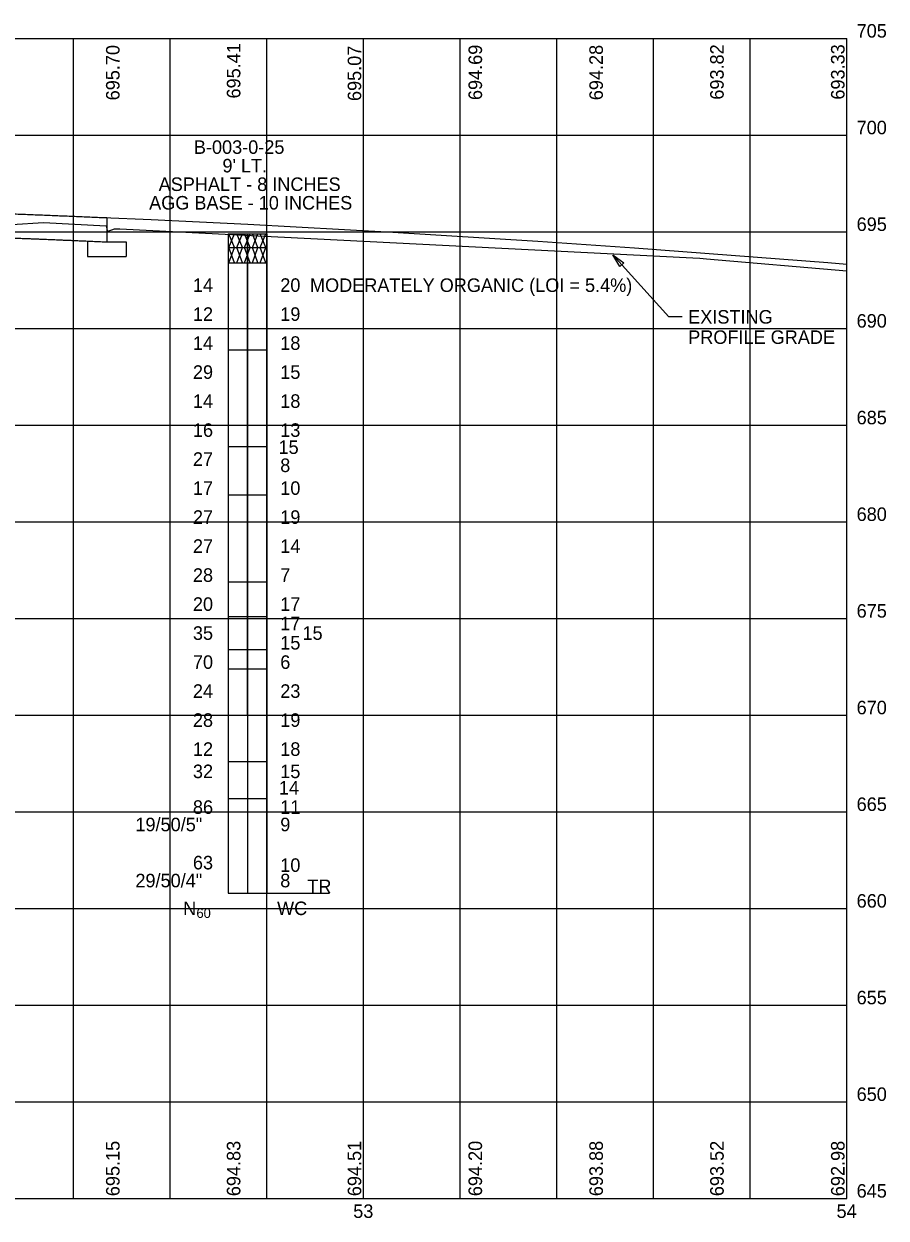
# Model space of a CAD drawing. Extents: x 991 to 1508, y 566 to 813.
# Drawn here: x 1329.7 to 1508.1, y 566 to 813 of the extents above; entities that cross this region are included whole.
import ezdxf

# ---------------------------------------------------------------- set-up
doc = ezdxf.new("R2010")
doc.units = 0
for name, color, linetype in [('BR_P_Gen_Approach_Slab', 7, 'Continuous'), ('Default', 7, 'Continuous'), ('GT_Project_Soil_Boring', 7, 'Continuous'), ('GT_Project_Soil_Layers', 7, 'Continuous'), ('GT_Project_Text', 7, 'Continuous'), ('GT_Project_Text_2', 7, 'Continuous'), ('PF_P_Grade_Line', 7, 'Continuous'), ('PF_P_Sta_Elev_Text', 7, 'Continuous'), ('PF_P_Text_Strip_Grades_20', 7, 'Continuous'), ('PF_X_Ground_Line', 7, 'Continuous'), ('PF_X_Text_Strip_Grade', 7, 'Continuous'), ('SC_Scratch1', 7, 'Continuous'), ('SH_Major_Grid_Line', 7, 'Continuous'), ('SH_Named_Boundary', 7, 'Continuous'), ('SH_Text', 7, 'Continuous')]:
    doc.layers.add(name, color=color, linetype=linetype)

msp = doc.modelspace()

# ---------------------------------------------------------------- linework, layer by layer
at = {"layer": 'BR_P_Gen_Approach_Slab'}
for p, q in [((1346.87, 772.95), (1346.87, 767.94)), ((1342.87, 768.11), (1342.87, 764.94)), ((1346.87, 767.94), (1350.87, 767.94)), ((1350.87, 767.94), (1350.87, 764.94)), ((1342.87, 764.94), (1350.87, 764.94))]:
    msp.add_line(p, q, dxfattribs=at)
for points in [[(1321.87, 773.95), (1334.37, 773.49), (1346.87, 772.95)], [(1323.63, 768.88), (1331.31, 768.6), (1338.98, 768.28), (1346.87, 767.94)]]:
    msp.add_open_spline(points, degree=2, dxfattribs=at)
at = {"layer": 'Default'}
msp.add_lwpolyline([(1326.04, 773.8), (1336.04, 773.4), (1346.04, 772.98), (1356.04, 772.54), (1366.04, 772.07), (1376.04, 771.57), (1386.04, 771.05), (1396.04, 770.5), (1406.04, 769.93), (1416.04, 769.34), (1426.04, 768.71), (1436.04, 768.07), (1446.04, 767.39), (1456.04, 766.69), (1466.04, 765.97), (1476.04, 765.22), (1486.04, 764.45), (1496.04, 763.64), (1500, 763.32)], dxfattribs=at)
at = {"layer": 'GT_Project_Soil_Boring'}
for p, q in [((1371.95, 769.6), (1379.95, 769.6)), ((1371.95, 769.6), (1371.95, 633.2)), ((1375.95, 769.6), (1375.95, 633.2)), ((1379.95, 769.6), (1379.95, 633.2)), ((1371.95, 766.8), (1379.95, 766.8)), ((1371.95, 763.6), (1379.95, 763.6)), ((1371.95, 745.6), (1379.95, 745.6)), ((1371.95, 725.6), (1379.95, 725.6)), ((1371.95, 715.6), (1379.95, 715.6)), ((1371.95, 697.6), (1379.95, 697.6)), ((1371.95, 690.4), (1379.95, 690.4)), ((1371.95, 683.6), (1379.95, 683.6)), ((1371.95, 679.6), (1379.95, 679.6)), ((1371.95, 660.4), (1379.95, 660.4)), ((1371.95, 652.8), (1379.95, 652.8)), ((1371.95, 633.2), (1379.95, 633.2))]:
    msp.add_line(p, q, dxfattribs=at)
at = {"layer": 'GT_Project_Soil_Layers'}
for p, q in [((1372.14, 766.8), (1373.29, 769.6)), ((1373.29, 766.8), (1372.14, 769.6)), ((1373.76, 766.8), (1374.91, 769.6)), ((1374.91, 766.8), (1373.76, 769.6)), ((1375.37, 766.8), (1376.53, 769.6)), ((1376.53, 766.8), (1375.37, 769.6)), ((1376.99, 766.8), (1378.14, 769.6)), ((1378.14, 766.8), (1376.99, 769.6)), ((1378.61, 766.8), (1379.76, 769.6)), ((1379.76, 766.8), (1378.61, 769.6)), ((1371.95, 766.8), (1371.95, 766.8)), ((1372.14, 763.6), (1373.29, 766.8)), ((1373.29, 763.6), (1372.14, 766.8)), ((1373.76, 763.6), (1374.91, 766.8)), ((1374.91, 763.6), (1373.76, 766.8)), ((1375.37, 763.6), (1376.53, 766.8)), ((1376.53, 763.6), (1375.37, 766.8)), ((1376.99, 763.6), (1378.14, 766.8)), ((1378.14, 763.6), (1376.99, 766.8)), ((1378.61, 763.6), (1379.76, 766.8)), ((1379.76, 763.6), (1378.61, 766.8)), ((1371.95, 763.6), (1371.95, 763.6))]:
    msp.add_line(p, q, dxfattribs=at)
at = {"layer": 'GT_Project_Text'}
for p, q in [((1379.95, 633.2), (1392.95, 633.2)), ((1365.41, 630.06), (1365.41, 630.06))]:
    msp.add_line(p, q, dxfattribs=at)
at = {"layer": 'PF_P_Grade_Line'}
msp.add_lwpolyline([(1326.04, 773.8), (1336.04, 773.4), (1346.04, 772.98), (1356.04, 772.54), (1366.04, 772.07), (1376.04, 771.57), (1386.04, 771.05), (1396.04, 770.5), (1406.04, 769.93), (1416.04, 769.34), (1426.04, 768.71), (1436.04, 768.07), (1446.04, 767.39), (1456.04, 766.69), (1466.04, 765.97), (1476.04, 765.22), (1486.04, 764.45), (1496.04, 763.64), (1500, 763.32)], dxfattribs=at)
at = {"layer": 'PF_X_Ground_Line'}
msp.add_lwpolyline([(1320.6, 771.15), (1333.77, 771.98), (1333.77, 771.98), (1346.7, 771.24), (1346.76, 771.23), (1346.95, 770.29), (1346.98, 770.31), (1347.13, 770.16), (1348.48, 770.67), (1349.58, 770.61), (1468.08, 764.61), (1469.54, 764.54), (1470.97, 764.42), (1500, 761.92)], dxfattribs=at)
at = {"layer": 'SC_Scratch1'}
msp.add_lwpolyline([(1300, 670), (1375.95, 670), (1375.95, 769.6)], dxfattribs=at)
at = {"layer": 'SH_Major_Grid_Line'}
for p, q in [((1000, 810), (1500, 810)), ((1000, 810), (1500, 810)), ((1000, 810), (1500, 810)), ((1340, 570), (1340, 810)), ((1340, 570), (1340, 810)), ((1360, 570), (1360, 810)), ((1360, 570), (1360, 810)), ((1380, 670), (1380, 810)), ((1380, 570), (1380, 810)), ((1400, 570), (1400, 810)), ((1400, 570), (1400, 810)), ((1420, 570), (1420, 810)), ((1420, 570), (1420, 810)), ((1440, 570), (1440, 810)), ((1440, 570), (1440, 810)), ((1460, 570), (1460, 810)), ((1460, 570), (1460, 810)), ((1480, 570), (1480, 810)), ((1480, 570), (1480, 810)), ((1500, 570), (1500, 810)), ((1500, 570), (1500, 810)), ((1000, 790), (1500, 790)), ((1000, 790), (1500, 790)), ((1000, 770), (1500, 770)), ((1000, 770), (1500, 770)), ((1000, 750), (1500, 750)), ((1000, 750), (1500, 750)), ((1000, 730), (1500, 730)), ((1000, 730), (1500, 730)), ((1000, 710), (1500, 710)), ((1000, 710), (1500, 710)), ((1000, 690), (1500, 690)), ((1000, 690), (1500, 690)), ((1000, 670), (1500, 670)), ((1000, 650), (1500, 650)), ((1000, 630), (1500, 630)), ((1000, 610), (1500, 610)), ((1000, 590), (1500, 590)), ((1000, 570), (1500, 570))]:
    msp.add_line(p, q, dxfattribs=at)
at = {"layer": 'SH_Named_Boundary'}
msp.add_line((1500, 570), (1500, 810), dxfattribs=at)
at = {"layer": 'SH_Text'}
for p in [(1451.54, 765.29), (1465.93, 752.43)]:
    msp.add_line(p, (1463.13, 752.43), dxfattribs=at)
msp.add_lwpolyline([(1453, 762.83), (1451.54, 765.29), (1453.83, 763.58)], close=True, dxfattribs=at)

# ---------------------------------------------------------------- texts
at = {"layer": 'GT_Project_Text'}
for s, height, p in [('B-003-0-25', 2.8, (1364.88, 786.15)), ('ASPHALT - 8 INCHES', 2.8, (1357.59, 778.47)), ('AGG BASE - 10 INCHES', 2.8, (1355.62, 774.63)), ('14', 2.8, (1364.68, 757.6)), ('20', 2.8, (1382.75, 757.6)), ('12', 2.8, (1364.68, 751.6)), ('19', 2.8, (1382.75, 751.6)), ('14', 2.8, (1364.68, 745.6)), ('18', 2.8, (1382.75, 745.6)), ('29', 2.8, (1364.68, 739.6)), ('15', 2.8, (1382.75, 739.6)), ('14', 2.8, (1364.68, 733.6)), ('18', 2.8, (1382.75, 733.6)), ('16', 2.8, (1364.68, 727.6)), ('13', 2.8, (1382.75, 727.6)), ('15', 2.8, (1382.39, 724.07)), ('27', 2.8, (1364.68, 721.6)), ('8', 2.8, (1382.75, 720.32)), ('17', 2.8, (1364.68, 715.6)), ('10', 2.8, (1382.75, 715.6)), ('27', 2.8, (1364.68, 709.6)), ('19', 2.8, (1382.75, 709.6)), ('27', 2.8, (1364.68, 703.6)), ('14', 2.8, (1382.75, 703.6)), ('28', 2.8, (1364.68, 697.6)), ('7', 2.8, (1382.75, 697.6)), ('20', 2.8, (1364.68, 691.6)), ('17', 2.8, (1382.75, 691.6)), ('17', 2.8, (1382.75, 687.6)), ('35', 2.8, (1364.68, 685.6)), ('15', 2.8, (1387.35, 685.6)), ('15', 2.8, (1382.75, 683.6)), ('70', 2.8, (1364.68, 679.6)), ('6', 2.8, (1382.75, 679.6)), ('24', 2.8, (1364.68, 673.6)), ('23', 2.8, (1382.75, 673.6)), ('28', 2.8, (1364.68, 667.6)), ('19', 2.8, (1382.75, 667.6)), ('12', 2.8, (1364.68, 661.6)), ('18', 2.8, (1382.75, 661.6)), ('32', 2.8, (1364.68, 656.99)), ('15', 2.8, (1382.75, 656.99)), ('14', 2.8, (1382.47, 653.6)), ('86', 2.8, (1364.68, 649.6)), ('11', 2.8, (1382.75, 649.6)), ('19/50/5"', 2.8, (1352.78, 646)), ('9', 2.8, (1382.75, 646)), ('63', 2.8, (1364.68, 638.11)), ('10', 2.8, (1382.75, 637.6)), ('29/50/4"', 2.8, (1352.78, 634.4)), ('8', 2.8, (1382.75, 634.4)), ('TR', 2.8, (1388.35, 633.2)), ('N', 2.8, (1362.65, 628.66)), ('60', 2, (1365.41, 628.06)), ('WC', 2.8, (1382.09, 628.66))]:
    msp.add_text(s, height=height, dxfattribs=at).set_placement(p)
at = {"layer": 'GT_Project_Text_2'}
msp.add_text("9' LT.", height=2.8, dxfattribs=at).set_placement((1370.79, 782.31))
at = {"layer": 'PF_P_Sta_Elev_Text'}
for s, p in [('705', (1502, 810.2)), ('705', (1502, 810.2)), ('700', (1502, 790.2)), ('700', (1502, 790.2)), ('695', (1502, 770.2)), ('695', (1502, 770.2)), ('690', (1502, 750.2)), ('690', (1502, 750.2)), ('685', (1502, 730.2)), ('685', (1502, 730.2)), ('680', (1502, 710.2)), ('680', (1502, 710.2)), ('675', (1502, 690.2)), ('675', (1502, 690.2)), ('670', (1502, 670.2)), ('670', (1502, 670.2)), ('665', (1502, 650.2)), ('660', (1502, 630.2)), ('655', (1502, 610.2)), ('650', (1502, 590.2)), ('645', (1502, 570.2)), ('53', (1397.85, 566)), ('54', (1497.85, 566))]:
    msp.add_text(s, height=2.8, dxfattribs=at).set_placement(p)
at = {"layer": 'PF_P_Text_Strip_Grades_20'}
for s, p in [('695.70', (1349.5, 797.22)), ('695.70', (1349.5, 797.22)), ('695.41', (1374.5, 797.61)), ('695.41', (1374.5, 797.61)), ('695.07', (1399.5, 797.08)), ('695.07', (1399.5, 797.08)), ('694.69', (1424.5, 797.28)), ('694.69', (1424.5, 797.28)), ('694.28', (1449.5, 797.25)), ('694.28', (1449.5, 797.25)), ('693.82', (1474.5, 797.36)), ('693.82', (1474.5, 797.36)), ('693.33', (1499.5, 797.37)), ('693.33', (1499.5, 797.37))]:
    msp.add_text(s, height=2.8, rotation=90, dxfattribs=at).set_placement(p)
at = {"layer": 'PF_X_Text_Strip_Grade'}
for s, p in [('695.15', (1349.5, 570.5)), ('695.15', (1349.5, 570.5)), ('694.83', (1374.5, 570.5)), ('694.51', (1399.5, 570.5)), ('694.20', (1424.5, 570.5)), ('694.20', (1424.5, 570.5)), ('693.88', (1449.5, 570.5)), ('693.52', (1474.5, 570.5)), ('692.98', (1499.5, 570.5))]:
    msp.add_text(s, height=2.8, rotation=90, dxfattribs=at).set_placement(p)
at = {"layer": 'SH_Text'}
for s, p in [('MODERATELY ORGANIC (LOI = 5.4%)', (1388.9, 757.58)), ('EXISTING', (1467.15, 751.03)), ('PROFILE GRADE', (1467.15, 746.83))]:
    msp.add_text(s, height=2.8, dxfattribs=at).set_placement(p)

doc.saveas('drawing.dxf')
